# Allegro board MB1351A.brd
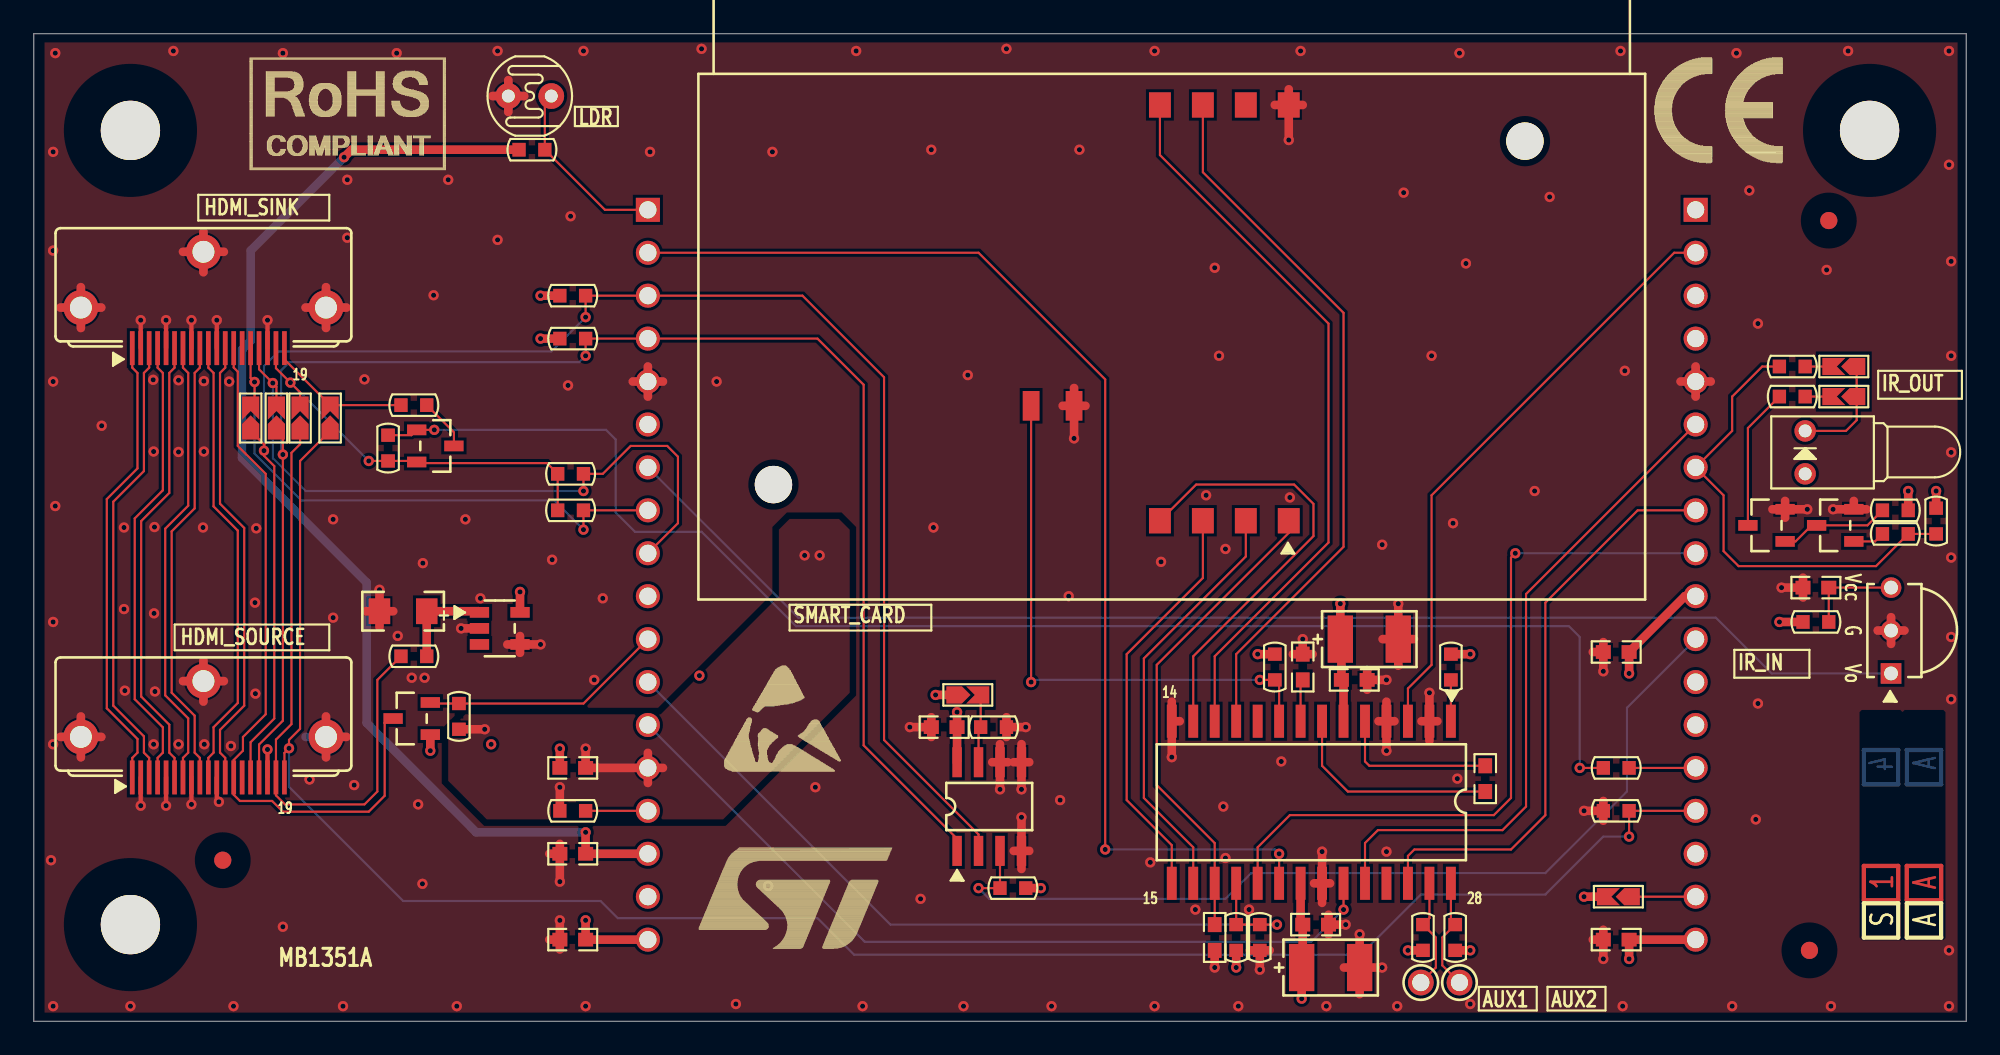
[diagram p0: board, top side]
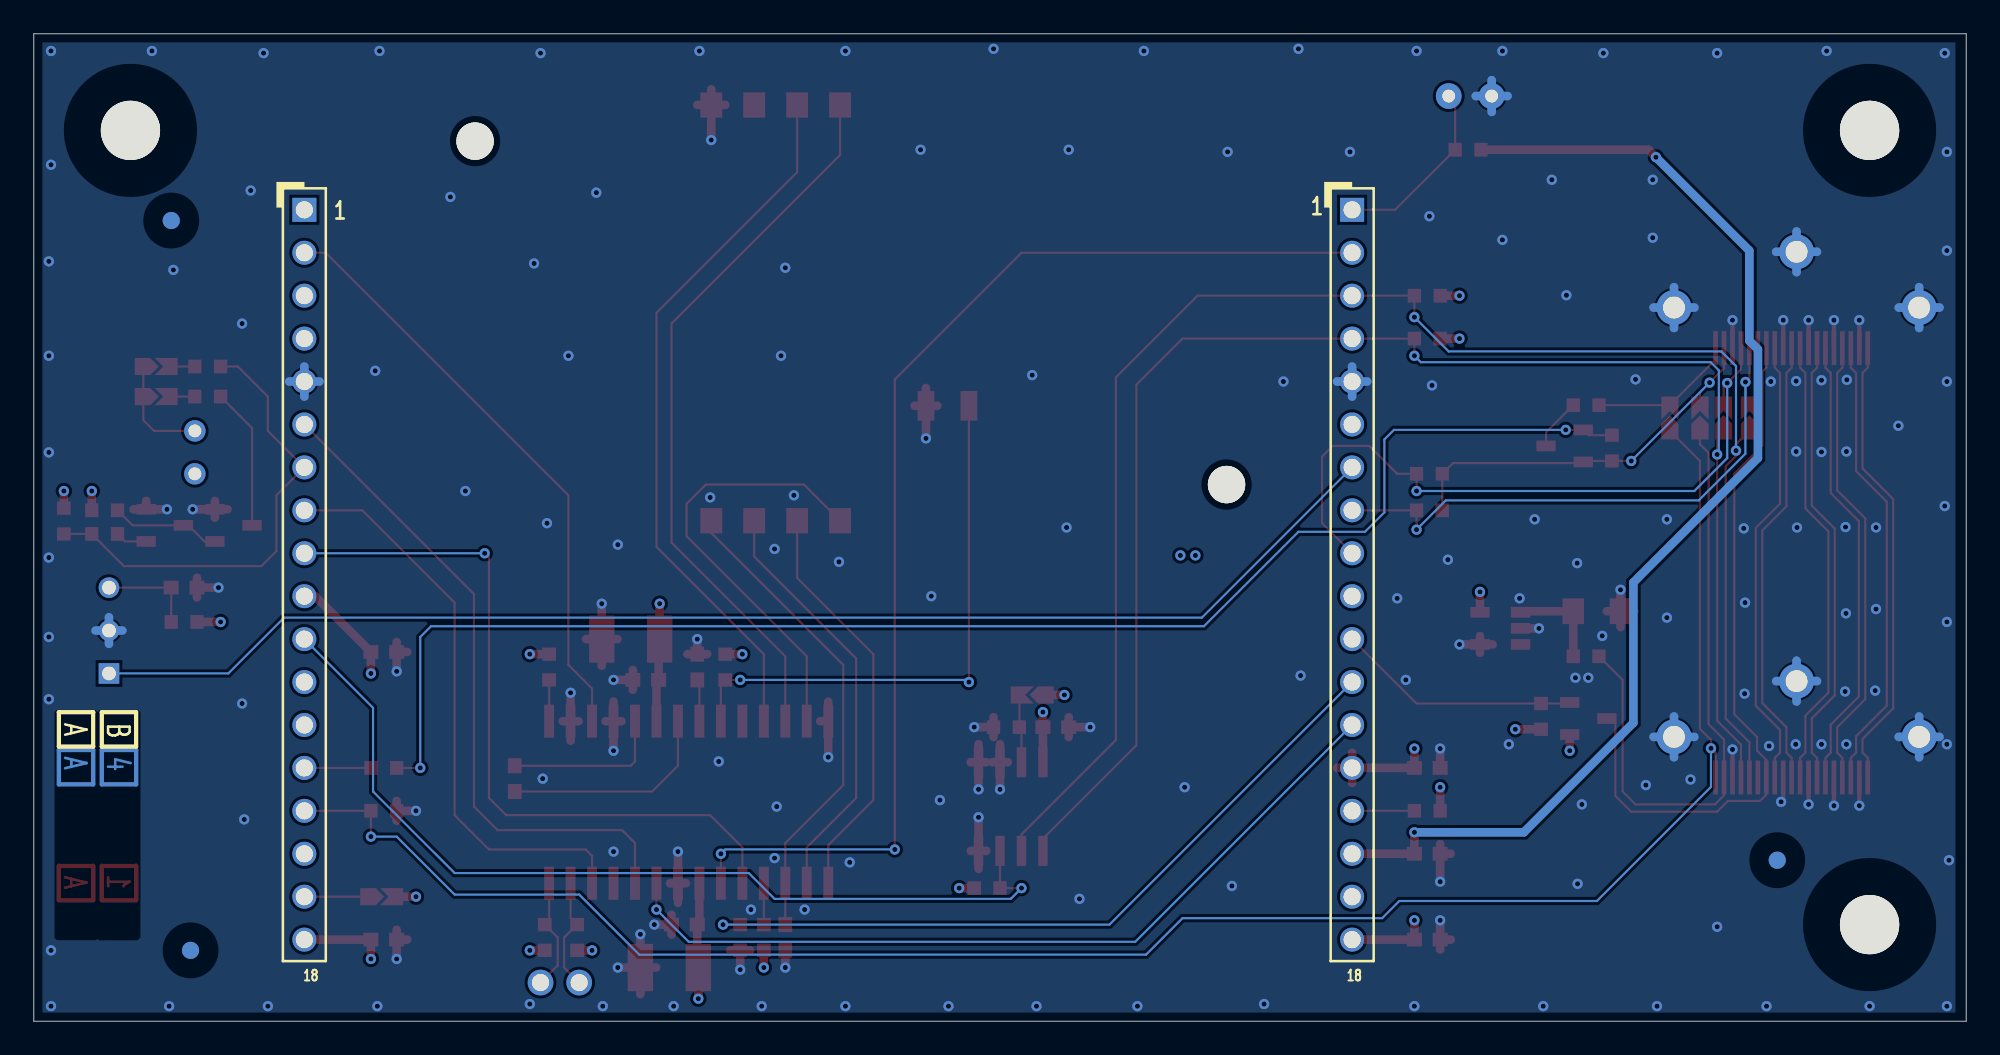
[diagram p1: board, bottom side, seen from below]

Outline 114.3 x 58.42 mm; copper layers: TOP, L2_GND, L3_VCC, BOTTOM. Coordinates in mm from the lower left corner of the outline.
Outline path: 0,58.42 114.3,58.42 114.3,0 0,0 0,58.42

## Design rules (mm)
net group TMDS_CLOCK: nets TMDS_CLOCK+ TMDS_CLOCK-
net group TMDS_DATA0: nets TMDS_DATA0+ TMDS_DATA0-
net group TMDS_DATA1: nets TMDS_DATA1+ TMDS_DATA1-
net group TMDS_DATA2: nets TMDS_DATA2+ TMDS_DATA2-

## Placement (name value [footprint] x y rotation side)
C1  4.7uF  [0603C]  105.41 25.65 180 top
C2  4.7uF  [TAN-A]  21.84 24.26 0 top
C3  47uF  [TAN-B]  78.99 22.61 0 top
C4  100nF  [0603C]  93.6 21.84 180 top
C5  100nF  [0603C]  75.06 20.95 90 top
C6  100nF  [0603C]  78.11 20.19 0 top
C7  100nF  [0603C]  53.85 17.4 0 top
C8  100nF  [0603C]  31.88 14.99 180 top
C9  100nF  [0603C]  85.85 14.35 90 top
C10  100nF  [0603C]  31.88 9.91 180 top
C11  100nF  [0603C]  75.82 5.71 0 top
C12  100nF  [0603C]  69.85 4.95 90 top
C13  100nF  [0603C]  31.88 4.83 180 top
C14  100nF  [0603C]  93.6 4.83 180 top
C15  47uF  [TAN-B]  76.71 3.17 0 top
CN1  HD119F-3A09200  [HDMI_19SM_3HD_V_CPT]  10.03 43.31 0 top
CN2  C816  [SAM_C816]  70.42 41.91 90 top
CN3  HD119F-3A09200  [HDMI_19SM_3HD_V_CPT]  10.03 17.91 0 top
CN4  Header 18X1_Female  [SKT_1X18_2R54]  98.3 48.01 270 bottom
CN5  Header 18X1_Female  [SKT_1X18_2R54]  36.32 48.01 270 bottom
D1  TSOP34836  [IR1_3TH_2R54_REV]  109.86 23.11 270 top
LD1  SFH409-2  [D0_1L]  104.78 33.66 90 top
NOREF  -  []  0 0 0 top
NOREF#2  -  []  392.18 -91.69 0 top
NOREF#3  -  []  112.57 8.17 90 top
NOREF#4  -  [unnamed#2]  108.58 52.7 0 top
NOREF#5  -  [unnamed#2]  106.17 47.37 0 top
NOREF#6  -  [unnamed#2]  11.18 9.53 0 top
NOREF#7  -  [unnamed#2]  5.71 52.7 0 top
NOREF#8  -  []  110.03 8.17 90 top
NOREF#9  -  [unnamed#2]  5.71 5.71 0 top
NOREF#10  -  []  -3.68 136.27 0 top
NOREF#11  -  []  228.6 109.47 0 top
NOREF#12  -  [unnamed#2]  105.03 4.19 0 top
NOREF#13  -  []  137.92 130.94 0 top
NOREF#14  -  []  -1.65 -33.66 0 top
NOREF#15  -  [unnamed#2]  106.17 47.37 180 bottom
NOREF#16  -  [unnamed#2]  11.18 9.53 180 bottom
NOREF#17  -  [unnamed#2]  105.03 4.19 180 bottom
R1  VT9ON1  [PVT901]  29.34 54.74 90 top
R2  8.2K  [0603R]  29.46 51.56 180 top
R3  1.8K  [0603R]  31.88 42.93 180 top
R4  1.8K  [0603R]  31.88 40.39 180 top
R5  100  [0603R]  104.01 38.73 180 top
R6  22  [0603R]  104.01 36.96 0 top
R7  1K  [0603R]  22.48 36.45 0 top
R8  1K  [0603R]  20.95 33.91 90 top
R9  47K  [0603R]  31.75 32.38 180 top
R10  47K  [0603R]  31.75 30.23 180 top
R11  10K  [0603R]  110.11 30.23 0 top
R12  10K  [0603R]  112.52 29.59 270 top
R13  1K  [0603R]  110.11 28.83 180 top
R14  100  [0603R]  105.41 23.62 180 top
R15  0  [0603R]  22.48 21.59 180 top
R16  100K  [0603R]  73.41 20.95 270 top
R17  4.7K  [0603R]  83.82 20.95 270 top
R18  27K  [0603R]  25.15 18.03 270 top
R19  10K  [0603R]  56.77 17.4 180 top
R20  1K  [0603R]  93.6 14.99 180 top
R21  20K  [0603R]  31.88 12.45 0 top
R22  1M  [0603R]  93.6 12.45 0 top
R23  10K  [0603R]  57.91 7.87 0 top
R24  10K[N_A]  [0603R]  71.12 4.95 90 top
R25  10K[N_A]  [0603R]  72.52 4.95 270 top
R26  10K  [0603R]  82.17 4.95 90 top
R27  10K  [0603R]  84.07 4.95 90 top
SB1  Solder Bridge OFF  [SB_0603]  107.06 38.73 0 top
SB2  Solder Bridge ON  [SB_0603]  107.06 36.96 0 top
SB3  Solder Bridge OFF  [SB_0603]  12.83 35.69 270 top
SB4  Solder Bridge OFF  [SB_0603]  14.35 35.69 270 top
SB5  Solder Bridge OFF  [SB_0603]  15.75 35.69 270 top
SB6  Solder Bridge OFF  [SB_0603]  17.53 35.69 270 top
SB7  Solder Bridge OFF  [SB_0603]  55.24 19.3 180 top
SB8  Solder Bridge ON  [SB_0603]  93.73 7.37 0 top
T1  9012  [SOT-23]  23.75 34.04 180 top
T2  9013  [SOT-23]  102.49 29.34 0 top
T3  9013  [SOT-23]  106.55 29.34 0 top
T4  2N7002  [SOT-23]  22.35 17.91 0 top
TP1  AUX1  [TP]  82.04 2.29 180 top
TP2  AUX2  [TP]  84.33 2.29 180 top
U1  STMPS2141STR_54  [SOT23-5]  27.56 23.24 270 top
U2  ST8024LACDR  [SOIC28W_1R27_17R9X10R325]  75.56 12.95 180 top
U3  STLM75M2F  [SOIC8_1R27_4R9X6]  56.52 12.7 0 top

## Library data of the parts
C1 C4-C14 = 0603C
C2 = TAN-A
C3 C15 = TAN-B
CN1 CN3 = HDMI_19SM_3HD_V_CPT
CN2 = SAM_C816
CN4 CN5 = SKT_1X18_2R54
D1 = IR1_3TH_2R54_REV
LD1 = D0_1L
R1 = PVT901
R2-R27 = 0603R
SB1-SB8 = SB_0603
T1-T4 = SOT-23
TP1 TP2 = TP
U1 = SOT23-5
U2 = SOIC28W_1R27_17R9X10R325
U3 = SOIC8_1R27_4R9X6

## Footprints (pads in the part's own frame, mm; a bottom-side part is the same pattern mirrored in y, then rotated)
0603C
  rect 0.889x0.813 smd: 1(-0.762,0) 2(0.762,0)
0603R
  rect 0.787x0.813 smd: 1(-0.762,0) 2(0.762,0)
D0_1L
  round 1.27 hole 0.762: 1(-1.27,0) 2(1.27,0)
HDMI_19SM_3HD_V_CPT
  rect 0.279x2.007 smd: 1(-4.21,-3.485) 2(-3.71,-3.485) 3(-3.21,-3.485) 4(-2.71,-3.485) 5(-2.21,-3.485) 6(-1.71,-3.485) 7(-1.21,-3.485) 8(-0.71,-3.485) 9(-0.21,-3.485) 10(0.29,-3.485) 11(0.79,-3.485) 12(1.29,-3.485) 13(1.79,-3.485) 14(2.29,-3.485) 15(2.79,-3.485) 16(3.29,-3.485) 17(3.79,-3.485) 18(4.29,-3.485) 19(4.79,-3.485)
  round 2.057 hole 1.295: 20(-7.25,-1.085) 21(0,2.215) 22(7.25,-1.085)
IR1_3TH_2R54_REV
  rect 1.219x1.219 hole 0.813: 1(2.54,0)
  round 1.219 hole 0.813: 2(0,0) 3(-2.54,0)
PVT901
  round 1.524 hole 0.762: 1(0,1.27) 2(0,-1.27)
SAM_C816
  round 2.21 hole 2.21 unplated: (-10.16,26.67) (10.16,-17.78)
  rect 1.499x1.295 smd: 1(-12.3,-3.81) 2(-12.3,-1.27) 3(-12.3,1.27) 4(-12.3,3.81) 5(12.3,-3.81) 6(12.3,-1.27) 7(12.3,1.27) 8(12.3,3.81)
  rect 1.753x0.991 smd: 17(-5.5,8.89) 18(-5.5,11.43)
SB_0603
  round 0.152 smd: 1(-0.762,0) 2(0.762,0)
SKT_1X18_2R54
  rect 1.422x1.422 hole 1.016: 1(0,0)
  round 1.422 hole 1.016: 2(2.54,0) 3(5.08,0) 4(7.62,0) 5(10.16,0) 6(12.7,0) 7(15.24,0) 8(17.78,0) 9(20.32,0) 10(22.86,0) 11(25.4,0) 12(27.94,0) 13(30.48,0) 14(33.02,0) 15(35.56,0) 16(38.1,0) 17(40.64,0) 18(43.18,0)
SOIC8_1R27_4R9X6
  rect 0.559x1.778 smd: 1(-1.905,-2.624) 2(-0.635,-2.624) 3(0.635,-2.624) 4(1.905,-2.624) 5(1.905,2.624) 6(0.635,2.624) 7(-0.635,2.624) 8(-1.905,2.624)
SOIC28W_1R27_17R9X10R325
  rect 0.584x1.956 smd: 1(-8.255,-4.795) 2(-6.985,-4.795) 3(-5.715,-4.795) 4(-4.445,-4.795) 5(-3.175,-4.795) 6(-1.905,-4.795) 7(-0.635,-4.795) 8(0.635,-4.795) 9(1.905,-4.795) 10(3.175,-4.795) 11(4.445,-4.795) 12(5.715,-4.795) 13(6.985,-4.795) 14(8.255,-4.795) 15(8.255,4.795) 16(6.985,4.795) 17(5.715,4.795) 18(4.445,4.795) 19(3.175,4.795) 20(1.905,4.795) 21(0.635,4.795) 22(-0.635,4.795) 23(-1.905,4.795) 24(-3.175,4.795) 25(-4.445,4.795) 26(-5.715,4.795) 27(-6.985,4.795) 28(-8.255,4.795)
SOT23-5
  rect 0.635x1.143 smd: 1(-0.95,-1.2) 2(0,-1.2) 3(0.95,-1.2) 4(0.95,1.2) 5(-0.95,1.2)
SOT-23
  rect 1.143x0.635 smd: 1(1.1,-0.95) 2(1.1,0.95) 3(-1.1,0)
TAN-A
  rect 1.27x1.524 smd: 1(1.397,0) 2(-1.397,0)
TAN-B
  rect 1.499x2.794 smd: 1(-1.714,0) 2(1.714,0)
TP
  round 1.524 hole 1.016: 1(0,0)
unnamed#2
  round 3.505 hole 3.505 unplated: (0,0)

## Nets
+3V3: C8.1 CN5.14 LD1.1 R14.2 R18.2 R21.1
+5V: C3.1 C4.1 C6.1 C7.2 CN4.10 R3.2 R4.2 SB7.2 SB8.1 T4.1 U1.5 U2.6 U3.8
GND: C1.2 C2.2 C3.2 C4.2 C5.2 C6.2 C7.1 C8.2 C10.2 C11.2 C12.1 C13.2 C14.2 C15.2 CN1.2 CN1.5 CN1.8 CN1.11 CN1.17 CN1.20 CN1.21 CN1.22 CN2.5 CN2.17 CN3.2 CN3.5 CN3.8 CN3.11 CN3.17 CN3.20 CN3.21 CN3.22 CN4.5 CN5.5 D1.2 R1.1 R19.1 R22.1 R25.2 T2.2 T3.2 U1.2 U1.4 U2.2 U2.4 U2.14 U2.22 U3.4 U3.5 U3.6
VDD: C11.1 C13.1 C14.1 C15.1 CN4.18 CN5.18 R11.2 R12.1 R16.1 R17.1 R23.2 R24.1 R26.1 R27.1 U2.21
VDD_ANA: C10.1 CN5.16 R2.2
HDMI_5V_SINK: CN1.18 R8.1 R9.2 R10.2 SB5.1 T1.2
HDMI_5V_SOURCE: C2.1 R15.1 U1.1
HDMI_CEC_3V3: CN5.11 R18.1 T4.2
HDMI_HPD_SINK: CN4.14 R20.1
HDMI_HPD_SOURCE_5V: CN3.19 CN4.15 R22.2 SB6.2
I2C1_SCL_5V: CN3.15 CN5.3 R3.1 SB3.2 U3.2
I2C1_SDA_5V: CN3.16 CN5.4 R4.1 SB4.2 U3.1
I2C2_SCL_5V: CN1.15 CN5.8 R10.1 SB3.1
I2C2_SDA_5V: CN1.16 CN5.9 R9.1 SB4.1
IR_IN: CN5.7 D1.1
IR_OUT: CN4.7 R5.2 R12.2 R13.1
LDR_OUT: CN5.1 R1.2 R2.1
NETC1_1: C1.1 D1.3 R14.1
NETC5_1: C5.1 U2.8
NETC9_1: C9.1 U2.7
NETC9_2: C9.2 U2.5
NETC12_2: C12.2 CN2.1 U2.17
NETCN1_13: CN1.13 CN3.13 T4.3
NETCN1_19: CN1.19 R7.1 SB6.1
NETCN2_2: CN2.2 U2.16
NETCN2_3: CN2.3 U2.15
NETCN2_4: CN2.4 U2.13
NETCN2_7: CN2.7 U2.11
NETCN2_8: CN2.8 U2.12
NETCN2_18: CN2.18 R16.2 U2.9
NETCN3_18: CN3.18 R15.2 SB5.2
NETCN4_17: CN4.17 SB8.2
NETCN5_15: CN5.15 R21.2
NETLD1_2: LD1.2 SB1.2 SB2.2
NETR5_1: R5.1 SB1.1
NETR6_1: R6.1 T2.3
NETR6_2: R6.2 SB2.1
NETR7_2: R7.2 T1.3
NETR8_2: R8.2 R20.2 T1.1
NETR11_1: R11.1 T2.1 T3.3
NETR13_2: R13.2 T3.1
NETR17_2: R17.2 U2.1
NETR19_2: R19.2 SB7.1 U3.7
NETR26_2: R26.2 TP1.1 U2.27
NETR27_2: R27.2 TP2.1 U2.28
SMARTCARD_1V8: CN5.12 R24.2 R25.1 U2.18
SMARTCARD_3_5V: CN4.2 U2.3
SMARTCARD_CLK: CN4.6 U2.24
SMARTCARD_CMDVCC: CN4.9 U2.19
SMARTCARD_IO: CN4.8 U2.26
SMARTCARD_OFF: CN5.13 U2.23
SMARTCARD_RST: CN5.2 U2.20
TEMPSENSOR_INT: CN4.11 R23.1 U3.3
TMDS_CLOCK+: CN1.10 CN3.10
TMDS_CLOCK-: CN1.12 CN3.12
TMDS_DATA0+: CN1.7 CN3.7
TMDS_DATA0-: CN1.9 CN3.9
TMDS_DATA1+: CN1.4 CN3.4
TMDS_DATA1-: CN1.6 CN3.6
TMDS_DATA2+: CN1.1 CN3.1
TMDS_DATA2-: CN1.3 CN3.3

Pads without a net: CN1 14; CN2 6; CN3 14; CN4 1 3 4 12 13 16; CN5 6 10 17; U1 3; U2 10 25

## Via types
v1: diameter 0.61, hole 0.305, TOP to BOTTOM, 228 vias

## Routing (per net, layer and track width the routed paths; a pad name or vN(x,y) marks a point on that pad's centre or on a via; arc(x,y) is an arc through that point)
+3V3: length 11.8
  TOP w0.508: R18.2 v1(26.67,17.27) ; CN5.14 37.21,14.99 ; CN5.14 36.32,14.1 ; CN5.14 36.32,15.88 ; CN5.14 32.64,14.99 v1(32.64,16.13) ; R21.1 v1(31.11,13.84) ; R14.2 v1(103.25,23.62)
  vias: v1(45.59,27.56) v1(46.48,27.56)
+5V: length 23.4
  TOP w0.508: v1(54.61,18.29) C7.2 U3.8 ; U2.6 77.47,20.07 C6.1 77.34,22.54 C3.1 v1(77.28,24.7) ; CN4.10 97.66,25.15 C4.1 v1(94.36,20.57) ; SB8.1 v1(91.69,7.37) ; R4.2 v1(29.97,40.39) ; SB7.2 v1(53.34,19.3) ; R3.2 v1(29.97,42.93) ; T4.1 v1(23.45,16) ; U1.5 v1(28.76,25.4)
GND: length 191.8
  TOP w0.254: CN1.8 v1(9.32,41.48) ; CN1.5 v1(7.82,41.48) ; CN1.2 v1(6.32,41.48) ; CN3.8 v1(9.32,12.83) ; CN3.5 v1(7.82,12.75) ; CN3.11 10.82,13.1 v1(10.95,12.98) ; CN1.17 v1(13.82,41.48) ; CN3.2 v1(6.32,12.75) ; CN1.11 v1(10.82,41.48) ; CN3.17 v1(13.82,16.08)
  TOP w0.508: 109.07,23.11 D1.2 ; D1.2 109.86,22.33 ; D1.2 110.64,23.11 ; D1.2 109.86,23.9 ; 30.49,4.83 C13.2 ; C13.2 31.11,4.24 ; C13.2 v1(31.11,5.97) ; C5.2 75.64,21.72 ; C5.2 v1(75.06,22.61) ; C5.2 74.47,21.72 ; 79.54,17.75 U2.4 ; U2.4 80.48,17.75 ; U2.4 v1(80.01,16) ; U2.4 80.01,18.91 ; 73.4,54.21 CN2.5 ; CN2.5 v1(74.23,52.14) ; CN2.5 75.06,54.21 ; CN2.5 74.23,55.14 ; C4.2 92.84,22.43 ; C4.2 92.21,21.84 ; C4.2 v1(92.84,20.7) ; CN3.22 18.49,16.82 ; CN3.22 17.28,18.03 ; CN3.22 17.28,15.61 ; 57.96,15.32 U3.5 ; U3.5 58.88,15.32 ; U3.5 58.42,16.39 ; U3.5 v1(58.42,13.72) ; CN2.17 62.2,36.41 ; CN2.17 61.53,37.46 ; CN2.17 60.86,36.41 ; CN2.17 v1(61.53,34.48) ; U2.14 67.78,17.75 ; U2.14 v1(67.31,15.62) ; U2.14 67.31,18.91 ; T3.2 108.4,30.29 ; T3.2 107.65,30.78 ; T3.2 v1(106.43,30.29) ; 78.42,1.6 C15.2 ; C15.2 77.49,3.17 ; C15.2 v1(79.76,3.17) ; C15.2 v1(78.42,5.14) ; 104.65,25.07 C1.2 ; C1.2 v1(103.38,25.65) ; C1.2 104.65,26.24 ; CN4.5 98.3,38.74 ; CN4.5 99.19,37.85 ; CN4.5 98.3,36.96 ; CN4.5 97.41,37.85 ; CN5.5 36.32,38.74 ; CN5.5 35.43,37.85 ; CN5.5 36.32,36.96 ; CN5.5 37.21,37.85 ; 19.63,24.26 C2.2 ; C2.2 21.26,24.26 ; C2.2 v1(20.45,25.53) ; C2.2 20.45,23.32 ; 103.59,29.79 T2.2 ; T2.2 103.59,30.78 ; T2.2 102.84,30.29 ; T2.2 v1(104.9,30.29) ; 57.53,16.81 R19.1 ; R19.1 57.53,17.98 ; R19.1 v1(58.67,17.4) ; U3.6 v1(57.15,13.72) ; U3.6 57.15,16.39 ; U3.6 57.61,15.32 ; U3.6 56.69,15.32 ; 58.42,9.01 U3.4 ; U3.4 v1(58.42,12.06) ; U3.4 57.96,10.08 ; U3.4 58.88,10.08 ; 8.83,20.12 CN3.21 ; CN3.21 10.03,21.33 ; CN3.21 11.24,20.12 ; CN3.21 10.03,18.91 ; 27.13,54.74 R1.1 ; R1.1 28.07,53.8 ; R1.1 28.07,55.68 ; R1.1 29.01,54.74 ; C3.2 v1(80.71,24.7) ; C3.2 80.71,21.03 ; C3.2 79.78,22.61 ; C3.2 81.64,22.61 ; CN1.22 18.49,42.22 ; CN1.22 16.08,42.22 ; CN1.22 17.28,43.43 ; CN1.22 17.28,41.01 ; C7.1 53.09,17.98 ; C7.1 53.09,16.81 ; C7.1 v1(51.82,17.4) ; 30.49,9.91 C10.2 ; C10.2 31.11,10.49 ; C10.2 v1(31.11,8.26) ; 8.83,45.52 CN1.21 ; CN1.21 10.03,44.31 ; CN1.21 11.24,45.52 ; CN1.21 10.03,46.73 ; C14.2 v1(92.84,3.68) ; C14.2 92.84,5.41 ; C14.2 92.21,4.83 ; C11.2 v1(77.6,5.71) ; C11.2 76.58,6.3 ; C11.2 76.58,5.13 ; 78.87,19.61 C6.2 ; C6.2 78.87,20.78 ; C6.2 v1(80.01,20.19) ; 28.01,22.29 U1.4 ; U1.4 28.76,21.8 ; U1.4 28.76,22.79 ; U1.4 v1(29.97,22.29) ; 75.73,8.16 U2.22 ; U2.22 v1(76.2,10.03) ; U2.22 76.2,7 ; U2.22 76.67,8.16 ; 82.08,17.75 U2.2 ; U2.2 v1(82.55,19.43) ; U2.2 83.02,17.75 ; U2.2 82.55,16.59 ; U1.2 v1(25.27,23.24) ; CN1.20 3.99,42.22 ; CN1.20 2.78,41.01 ; CN1.20 1.58,42.22 ; CN1.20 2.78,43.43 ; R22.1 92.84,13.03 ; R22.1 v1(91.69,12.45) ; R22.1 92.84,11.86 ; 2.78,15.61 CN3.20 ; CN3.20 3.99,16.82 ; CN3.20 2.78,18.03 ; CN3.20 1.58,16.82 ; C8.2 v1(31.11,16.13) ; R25.2 v1(72.52,3.05) ; R25.2 73.1,4.19 ; R25.2 71.93,4.19 ; C12.1 v1(69.85,3.17)
  BOTTOM w0.508: CN1.22 17.28,43.43 ; CN1.22 18.49,42.22 ; CN1.22 17.28,41.01 ; CN1.22 16.08,42.22 ; CN1.20 2.78,43.43 ; CN1.20 3.99,42.22 ; CN1.20 2.78,41.01 ; CN1.20 1.58,42.22 ; D1.2 109.86,23.9 ; D1.2 110.64,23.11 ; D1.2 109.07,23.11 ; D1.2 109.86,22.33 ; 2.78,15.61 CN3.20 ; CN3.20 3.99,16.82 ; CN3.20 1.58,16.82 ; CN3.20 2.78,18.03 ; 8.83,45.52 CN1.21 ; CN1.21 10.03,46.73 ; CN1.21 11.24,45.52 ; CN1.21 10.03,44.31 ; CN4.5 99.19,37.85 ; CN4.5 98.3,36.96 ; CN4.5 97.41,37.85 ; CN4.5 98.3,38.74 ; 27.13,54.74 R1.1 ; R1.1 28.07,55.68 ; R1.1 28.07,53.8 ; R1.1 29.01,54.74 ; 36.32,36.96 CN5.5 ; CN5.5 35.43,37.85 ; CN5.5 36.32,38.74 ; CN5.5 37.21,37.85 ; 8.83,20.12 CN3.21 ; CN3.21 11.24,20.12 ; CN3.21 10.03,21.33 ; CN3.21 10.03,18.91 ; CN3.22 17.28,18.03 ; CN3.22 18.49,16.82 ; CN3.22 16.08,16.82 ; CN3.22 17.28,15.61
  vias: v1(1.02,9.53) v1(1.14,51.44) v1(1.14,45.59) v1(1.14,37.85) v1(1.14,23.62) v1(1.14,16.38) v1(1.14,0.89) v1(1.27,57.28) v1(1.27,30.48) v1(4.01,35.23) v1(5.33,29.21) v1(5.33,24.38) v1(5.38,19.56) v1(5.71,0.89) v1(7.06,37.95) v1(7.09,33.71) v1(7.14,29.24) v1(7.11,24.13) v1(7.09,16.38) v1(7.16,19.51) v1(8.26,57.4) v1(8.56,37.92) v1(8.56,33.68) v1(8.56,16.38) v1(10.01,29.21) v1(10.06,37.87) v1(10.06,33.71) v1(10.08,16.38) v1(11.56,37.85) v1(11.66,16.28) v1(11.81,0.89) v1(13.08,24.77) v1(13.11,19.38) v1(13.16,29.16) v1(14.73,57.28) v1(14.73,5.59) v1(16.31,14.3) v1(17.7,29.69) v1(17.7,23.88) v1(18.29,0.89) v1(18.54,49.78) v1(18.54,46.35) v1(18.95,13.97) v1(19.56,37.97) v1(21.46,57.28) v1(21.53,22.8) v1(22.35,20.32) v1(22.73,12.83) v1(23.01,27.1) v1(22.99,8.13) v1(23.11,20.32) v1(23.65,42.95) v1(24.51,49.78) v1(25.02,0.89) v1(25.53,29.69) v1(26.42,25.02) v1(27.05,16.38) v1(27.43,57.4) v1(27.43,46.23) v1(30.66,27.3) v1(31.6,37.62) v1(31.75,47.62) v1(32.51,57.4) v1(32.64,0.89) v1(33.15,20.19) v1(33.66,25.02) v1(36.45,51.44) v1(39.37,20.45) v1(39.5,57.53) v1(40.39,37.85) v1(41.53,1.02) v1(43.43,8) v1(43.69,51.44) v1(46.23,13.84) v1(48.64,57.4) v1(49.02,0.89) v1(52.45,7.24) v1(53.09,51.56) v1(53.21,29.21) v1(54.99,0.89) v1(55.24,38.23) v1(57.53,57.53) v1(60.2,0.89) v1(60.71,13.08) v1(61.21,25.15) v1(61.85,51.56) v1(66.04,9.4) v1(66.29,57.4) v1(66.29,0.89) v1(66.67,27.18) v1(68.71,6.6) v1(69.34,31.11) v1(69.85,44.58) v1(70.1,39.37) v1(70.36,12.7) v1(70.48,27.94) v1(70.48,9.65) v1(71.25,0.89) v1(71.88,6.6) v1(73.79,15.37) v1(74.3,30.99) v1(74.93,57.4) v1(76.45,0.89) v1(79.76,28.19) v1(80.01,10.03) v1(80.64,0.89) v1(81.03,49.02) v1(82.68,39.37) v1(83.95,29.46) v1(84.2,14.35) v1(84.33,57.28) v1(84.71,44.83) v1(84.96,1.02) v1(88.77,31.37) v1(89.66,48.77) v1(93.85,57.4) v1(93.98,0.89) v1(94.11,38.48) v1(100.46,0.89) v1(100.71,57.28) v1(101.47,49.15) v1(101.85,11.94) v1(101.98,41.27) v1(101.98,18.8) v1(106.05,44.45) v1(106.3,0.89) v1(107.31,57.4) v1(113.28,57.4) v1(113.28,50.67) v1(113.28,4.19) v1(113.28,0.89) v1(113.41,44.96) v1(113.41,39.37) v1(113.41,33.66) v1(113.41,27.43) v1(113.41,22.73) v1(113.41,19.05)
VDD: length 24.8
  TOP w0.508: v1(32.64,5.97) 32.64,4.83 CN5.18 ; R11.2 v1(110.87,31.37) ; R12.1 v1(112.52,31.37) ; v1(94.36,3.68) C14.1 CN4.18 ; R27.1 v1(84.96,4.19) ; R17.1 v1(84.96,21.72) ; U2.21 74.93,5.84 C11.1 75.06,3.24 C15.1 v1(74.99,1.33) ; R16.1 v1(72.39,21.72) ; R23.2 v1(59.56,7.87) ; R26.1 v1(81.28,4.19) ; R24.1 v1(71.12,3.17)
VDD_ANA: length 70.1
  TOP w0.508: v1(32.64,11.18) 32.64,9.91 CN5.16 ; R2.2 18.8,51.56 v1(18.35,51.12)
  BOTTOM w0.508: v1(32.64,11.18) 26.16,11.18 19.68,17.65 19.68,25.96 12.32,33.32 12.32,39.75 12.83,40.26 12.83,45.59 v1(18.35,51.12)
HDMI_5V_SINK: length 24.2
  TOP w0.127: v1(19.81,33.15) R8.1 22.59,33.15 T1.2 22.71,33.02 30.35,33.02 R9.2 R10.2 ; CN1.18 14.32,38.64 v1(15.18,37.78) 15.75,37.21 SB5.1
  BOTTOM w0.127: v1(15.18,37.78) v1(19.81,33.15)
HDMI_5V_SOURCE: length 5.8
  TOP w0.508: R15.1 C2.1 26.29,24.26 U1.1
HDMI_CEC_3V3: length 14.5
  TOP w0.127: CN5.11 32.51,18.8 R18.1 23.51,18.8 T4.2
HDMI_HPD_SINK: length 3.9
  TOP w0.127: R20.1 CN4.14
HDMI_HPD_SOURCE_5V: length 115.6
  TOP w0.127: v1(94.36,10.92) R22.2 CN4.15 ; CN3.19 14.82,15.88 v1(15.09,16.15) 15.09,16.64 15.75,17.3 15.75,33.15 SB6.2
  BOTTOM w0.127: v1(94.36,10.92) 92.84,10.92 89.41,7.49 82.04,7.49 78.49,3.94 48.51,3.94 46.35,6.1 34.54,6.1 33.53,7.11 21.84,7.11 15.09,13.86 v1(15.09,16.15)
I2C1_SCL_5V: length 98.2
  TOP w0.127: SB3.2 13.63,34.12 13.63,34.12 v1(13.61,33.76) 13.61,33.45 14.22,32.84 14.22,17.91 12.82,16.51 CN3.15 ; v1(32.64,41.66) 32.64,42.93 CN5.3 45.47,42.93 50.29,38.1 50.29,16.64 55.88,11.05 U3.2
  BOTTOM w0.127: v1(32.64,41.66) 30.61,39.62 14.48,39.62 13.61,38.76 v1(13.61,33.76)
I2C1_SDA_5V: length 93.1
  TOP w0.127: CN3.16 13.32,16.37 14.73,17.78 v1(14.73,33.53) 14.73,34.54 SB4.2 ; U3.1 54.61,10.79 49.08,16.32 49.08,37.66 46.35,40.39 CN5.4 32.64,40.39 v1(32.64,39.37)
  BOTTOM w0.127: v1(14.73,33.53) 14.63,33.63 14.63,38.51 15.11,38.99 32.26,38.99 v1(32.64,39.37)
I2C2_SCL_5V: length 34.1
  TOP w0.127: CN1.15 12.82,38.05 v1(13.06,37.82) 13.06,36.69 12.82,36.45 SB3.1 ; CN5.8 R10.1 v1(32.51,29.08)
  BOTTOM w0.127: v1(13.06,37.82) 13.06,33.58 15.82,30.81 30.78,30.81 v1(32.51,29.08)
I2C2_SDA_5V: length 41.4
  TOP w0.127: CN1.16 13.32,38.57 v1(14.13,37.76) 14.35,37.54 SB4.1 ; CN5.9 38.1,29.46 38.1,33.4 37.47,34.04 35.31,34.04 33.66,32.38 R9.1 v1(32.51,31.37)
  BOTTOM w0.127: v1(14.13,37.76) 14.13,33.31 16.08,31.37 v1(32.51,31.37)
IR_IN: length 78.6
  BOTTOM w0.127: CN5.7 45.21,23.88 99.49,23.88 102.79,20.57 D1.1
IR_OUT: length 28
  TOP w0.127: R5.2 102.23,38.73 100.46,36.96 100.46,34.92 CN4.7 99.95,31.11 99.95,27.81 100.84,26.92 108.97,26.92 R13.1 R12.2
LDR_OUT: length 10.9
  TOP w0.127: CN5.1 33.78,48.01 R2.1 30.23,54.36 R1.2
NETC1_1: length 5.7
  TOP w0.127: D1.3 C1.1 R14.1
NETC5_1: length 2.5
  TOP w0.127: U2.8 74.93,20.07 C5.1
NETC9_1: length 12.9
  TOP w0.127: U2.7 76.2,15.11 77.72,13.59 C9.1
NETC9_2: length 9.6
  TOP w0.127: U2.5 78.74,15.37 78.99,15.11 85.85,15.11
NETC12_2: length 28.5
  TOP w0.127: C12.2 U2.17 69.85,10.54 66.42,13.97 66.42,21.08 74.23,28.89 CN2.1
NETCN1_13: length 42.6
  TOP w0.127: CN1.13 11.82,38.67 12.06,38.43 12.06,34.04 13.72,32.38 13.72,18.16 12.37,16.81 12.37,16 11.82,15.46 CN3.13 11.82,13.4 12.19,13.03 14.1,13.03 14.73,12.4 19.81,12.4 20.75,13.34 20.75,17.65 21.01,17.91 T4.3
NETCN1_19: length 8.7
  TOP w0.127: CN1.19 14.82,39.15 SB6.1 R7.1
NETCN2_2: length 25.2
  TOP w0.127: U2.16 68.58,10.29 65.66,13.21 65.66,21.46 71.69,27.49 CN2.2
NETCN2_3: length 24.4
  TOP w0.127: U2.15 67.31,10.41 64.64,13.08 64.64,21.72 69.15,26.22 CN2.3
NETCN2_4: length 26.2
  TOP w0.127: U2.13 68.58,21.59 75.69,28.7 75.69,30.61 74.55,31.75 68.75,31.75 CN2.4
NETCN2_7: length 42.5
  TOP w0.127: CN2.7 69.15,50.23 77.47,41.91 77.47,28.07 71.12,21.72 U2.11
NETCN2_8: length 43.4
  TOP w0.127: CN2.8 66.61,51.25 76.58,41.27 76.58,28.32 69.85,21.59 U2.12
NETCN2_18: length 33.4
  TOP w0.127: v1(72.52,20.19) R16.2 73.66,19.94 U2.9 ; v1(58.99,20.07) CN2.18
  BOTTOM w0.127: v1(72.52,20.19) 59.12,20.19 v1(58.99,20.07)
NETCN3_18: length 37.3
  TOP w0.127: R15.2 20.32,20.19 20.32,13.59 19.56,12.83 14.86,12.83 14.32,13.36 CN3.18 14.32,16.66 15.24,17.58 15.24,33.63 15.75,34.14 SB5.2
NETCN4_17: length 3.8
  TOP w0.127: SB8.2 CN4.17
NETCN5_15: length 3.7
  TOP w0.127: 32.64,12.45 CN5.15
NETLD1_2: length 6.5
  TOP w0.127: 104.78,34.92 107.19,34.92 107.82,35.56 SB2.2 SB1.2
NETR5_1: length 1.7
  TOP w0.127: 106.43,38.73 SB1.1 R5.1
NETR6_1: length 8.4
  TOP w0.127: T2.3 101.39,35.09 R6.1
NETR6_2: length 1.5
  TOP w0.127: R6.2 SB2.1
NETR7_2: length 3.1
  TOP w0.127: T1.3 24.85,34.84 R7.2
NETR8_2: length 87.4
  TOP w0.127: v1(23.69,34.99) T1.1 22.33,34.67 R8.2 ; R20.2 v1(91.44,14.99)
  BOTTOM w0.127: v1(91.44,14.99) 91.44,22.73 90.81,23.37 45.09,23.37 39.5,28.96 35.56,28.96 34.42,30.1 34.42,34.42 33.85,34.99 v1(23.69,34.99)
NETR11_1: length 6.5
  TOP w0.127: T2.1 104.21,28.39 105.16,29.34 T3.3 108.46,29.34 R11.1
NETR13_2: length 1.9
  TOP w0.127: T3.1 108.91,28.39 R13.2
NETR17_2: length 2.4
  TOP w0.127: R17.2 U2.1
NETR19_2: length 4
  TOP w0.127: U3.7 55.88,17.27 R19.2 SB7.1
NETR26_2: length 6.7
  TOP w0.127: TP1.1 82.93,3.17 82.93,4.95 R26.2 82.55,6.1 U2.27
NETR27_2: length 6.7
  TOP w0.127: TP2.1 83.31,3.3 83.31,4.95 R27.2 83.82,5.97 U2.28
SMARTCARD_1V8: length 48
  TOP w0.127: U2.18 R24.2 R25.1 v1(73.53,5.71)
  BOTTOM w0.127: v1(73.53,5.71) 50.67,5.71 CN5.12
SMARTCARD_3_5V: length 35.5
  TOP w0.127: U2.3 81.28,19.68 82.68,21.08 82.68,31.11 97.03,45.47 CN4.2
SMARTCARD_CLK: length 39.6
  TOP w0.127: U2.24 78.74,10.54 79.5,11.3 86.87,11.3 88.27,12.7 88.27,25.27 CN4.6
SMARTCARD_CMDVCC: length 43.6
  TOP w0.127: U2.19 72.39,10.29 74.3,12.19 86.36,12.19 87.38,13.21 87.38,27.43 v1(87.63,27.69)
  BOTTOM w0.127: CN4.9 v1(87.63,27.69)
SMARTCARD_IO: length 34.5
  TOP w0.127: U2.26 81.28,9.78 81.66,10.16 87.38,10.16 89.41,12.19 89.41,24.77 94.87,30.23 CN4.8
SMARTCARD_OFF: length 48.8
  TOP w0.127: U2.23 v1(77.47,6.6)
  BOTTOM w0.127: CN5.13 49.15,4.7 75.56,4.7 v1(77.47,6.6)
SMARTCARD_RST: length 70.1
  TOP w0.127: CN5.2 55.88,45.47 63.37,37.97 v1(63.37,10.16) ; U2.20 v1(73.66,9.91)
  BOTTOM w0.127: v1(73.66,9.91) 73.41,10.16 v1(63.37,10.16)
TEMPSENSOR_INT: length 55.4
  TOP w0.127: v1(55.88,7.87) R23.1 U3.3
  BOTTOM w0.127: CN4.11 94.23,18.54 94.23,13.59 89.41,8.76 72.01,8.76 70.48,7.24 56.52,7.24 v1(55.88,7.87)
TMDS_CLOCK+: length 26.8
  TOP w0.13: CN3.10 10.32,15.58 10.63,15.89 10.63,17.39 12.06,18.83 12.06,29.03 10.63,30.46 10.63,38.36 10.32,38.66 CN1.10
TMDS_CLOCK-: length 26.8
  TOP w0.13: CN1.12 11.32,38.66 11.01,38.36 11.01,30.62 12.45,29.18 12.45,18.67 11.01,17.24 11.01,15.89 11.32,15.58 CN3.12
TMDS_DATA0+: length 26.8
  TOP w0.13: CN1.7 8.82,38.66 9.13,38.36 9.13,30.5 7.77,29.14 7.77,19.28 9.13,17.92 9.13,15.89 8.82,15.58 CN3.7
TMDS_DATA0-: length 26.8
  TOP w0.13: CN3.9 9.82,15.58 9.51,15.89 9.51,18.08 8.15,19.44 8.15,28.98 9.51,30.34 9.51,38.36 9.82,38.66 CN1.9
TMDS_DATA1+: length 27
  TOP w0.13: CN1.4 7.32,38.66 7.63,38.36 7.63,31.41 5.97,29.75 5.97,19.05 7.63,17.39 7.63,15.89 7.32,15.58 CN3.4
TMDS_DATA1-: length 27
  TOP w0.13: CN3.6 8.32,15.58 8.01,15.89 8.01,17.54 6.35,19.21 6.35,29.59 8.01,31.25 8.01,38.36 8.32,38.66 CN1.6
TMDS_DATA2+: length 27.2
  TOP w0.13: CN3.1 5.82,15.58 6.13,15.89 6.13,16.7 4.32,18.51 4.32,30.89 6.13,32.71 6.13,38.36 5.82,38.66 CN1.1
TMDS_DATA2-: length 27.2
  TOP w0.13: CN1.3 6.82,38.66 6.51,38.36 6.51,32.55 4.7,30.73 4.7,18.67 6.51,16.85 6.51,15.89 6.82,15.58 CN3.3

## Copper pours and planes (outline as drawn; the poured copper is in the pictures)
+3V3 on TOP: 26.8,11.94 24.51,14.22 24.51,17.14 25.53,18.16 37.08,18.16 44.07,25.15 44.07,29.08 44.7,29.72 47.62,29.72 48.26,29.08 48.26,19.43 40.77,11.94 32.51,11.94 32.51,12.95 31.5,12.95 31.5,11.94 ; 1 cut-out
+3V3 on L3_VCC: 44.06,34.68 51.79,42.42 113.79,42.42 113.79,32.13 106.07,32.13 105.16,31.22 105.16,21.72 103.12,21.72 100.58,24.26 100.58,27.54 90.91,37.21 64.92,37.21 52.85,25.15 45.59,25.15 44.06,26.68
+5V on TOP (solid shape): 55.4,19.3 54.9,18.8 53.98,18.8 53.98,19.81 54.9,19.81
+5V on TOP (solid shape): 93.31,7.37 93.82,6.86 92.46,6.86 92.46,7.87 93.82,7.87
+5V on L3_VCC: 0.51,0.51 0.51,57.91 113.79,57.91 113.79,42.93 51.58,42.93 43.43,34.78 43.43,26.54 45.47,24.51 52.94,24.51 65.13,36.7 90.7,36.7 100.08,27.33 100.08,24.13 103,21.21 105.16,21.21 105.16,8.36 103.27,6.48 91.55,6.48 90.93,7.09 90.93,22.08 90.15,22.86 72.16,22.86 71.5,22.2 71.5,10.52 70.13,9.14 50.69,9.14 48.66,7.11 32.28,7.11 31.62,6.46 31.62,0.51
GND on TOP: 0.64,0.51 0.64,57.91 113.79,57.91 113.79,0.51 ; 1 cut-out
GND on BOTTOM: 0.64,0.51 0.64,57.91 113.79,57.91 113.79,0.51
GND on L2_GND: 0.51,0.51 0.51,57.91 113.79,57.91 113.79,0.51
VDD on L3_VCC: 32.13,0.51 32.13,6.24 32.49,6.6 48.87,6.6 50.91,8.64 70.34,8.64 72.01,10.31 72.01,21.99 72.37,22.35 89.94,22.35 90.42,21.87 90.42,6.88 91.33,5.97 103.48,5.97 105.66,8.15 105.66,31.01 106.28,31.62 113.79,31.62 113.79,0.51
HDMI_5V_SINK on TOP (solid shape): 16.26,35.6 15.75,36.1 15.24,35.59 15.24,36.96 16.26,36.96
HDMI_HPD_SOURCE_5V on TOP (solid shape): 18.03,35.34 18.03,34.42 17.02,34.42 17.02,35.34 17.53,35.85
I2C1_SCL_5V on TOP (solid shape): 13.34,35.34 13.34,34.42 12.32,34.42 12.32,35.34 12.83,35.85
I2C1_SDA_5V on TOP (solid shape): 14.86,35.34 14.86,34.42 13.84,34.42 13.84,35.34 14.35,35.85
I2C2_SCL_5V on TOP (solid shape): 13.34,35.6 12.83,36.1 12.32,35.59 12.32,36.96 13.34,36.96
I2C2_SDA_5V on TOP (solid shape): 14.86,35.6 14.35,36.1 13.84,35.59 13.84,36.96 14.86,36.96
NETCN1_19 on TOP (solid shape): 18.03,35.6 17.53,36.1 17.02,35.59 17.02,36.96 18.03,36.96
NETCN3_18 on TOP (solid shape): 16.26,35.34 16.26,34.42 15.24,34.42 15.24,35.34 15.75,35.85
NETCN4_17 on TOP (solid shape): 95,6.86 94.08,6.86 93.57,7.37 94.08,7.87 95,7.87
NETLD1_2 on TOP (solid shape): 108.33,38.23 107.41,38.23 106.9,38.73 107.41,39.24 108.33,39.24
NETLD1_2 on TOP (solid shape): 108.33,36.45 107.41,36.45 106.9,36.96 107.41,37.47 108.33,37.47
NETR5_1 on TOP (solid shape): 106.65,38.74 107.16,38.23 105.79,38.23 105.79,39.24 107.15,39.24
NETR6_2 on TOP (solid shape): 106.65,36.96 107.16,36.45 105.79,36.45 105.79,37.47 107.15,37.47
NETR19_2 on TOP (solid shape): 56.52,18.8 55.15,18.8 55.66,19.3 55.15,19.81 56.52,19.81

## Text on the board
Ref Des/Silkscreen Bottom: B | A
Ref Des/Silkscreen Top: HDMI_SOURCE | HDMI_SINK | LDR | SMART_CARD | AUX1 | AUX2 | IR_IN | IR_OUT | MB1351A | S | A
User.23: 1,4 | 5.1 | 9.9 | N/A | 100 OHM | +/-10%
User.34: FIGURE | SIZE | 12.0 | 30.0 | 32.0 | 40.0 | 51.0 | 87.0 | 138.0 | DRILL CHART: TOP to BOTTOM | ALL UNITS ARE IN MILS | TOLERANCE | +3.0/-3.0 | +2.0/-2.0 | PLATED | NON-PLATED | QTY | 228 | 4 | 3 | 38 | 6 | 2
